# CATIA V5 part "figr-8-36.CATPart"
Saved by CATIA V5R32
Part number: Part1
Bounding box of the stored display mesh (mm): x -75 to 75, y -75 to 75, z 0 to 20
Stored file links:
  D:\PROJECTS\Project 2022\CATIA V5 6R 2022\Resources\Part Files\c08_catia_v5_6r2022_prt\figr-8-36.CATPart
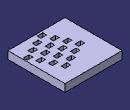
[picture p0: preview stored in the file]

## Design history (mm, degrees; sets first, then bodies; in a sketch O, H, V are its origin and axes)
Body1 (main body)
  Sketch1 on xy-plane, origin (0, 0, 0), H (1, 0, 0), V (0, 1, 0)
    line L1 (-75, 75) -> (75, 75)
    line L2 (75, 75) -> (75, -75)
    line L3 (75, -75) -> (-75, -75)
    line L4 (-75, -75) -> (-75, 75)
    axis line L5 (75, -75) -> (-75, 75)
    length L3 = 150
    length L2 = 150
    horizontal: L1 H, L3 H
    vertical: L2 V, L4 V
    midpoint: O L5
  Pad1: profile Sketch1, direction (0, 0, 1), length 20
  Sketch2 on face of Pad1, origin (0, 0, 20), H (1, 0, 0), V (0, 1, 0)
    line L1 (25, 40) -> (40, 40)
    line L2 (40, 40) -> (40, 30)
    line L3 (40, 30) -> (25, 30)
    line L4 (25, 30) -> (25, 40)
    reference projected line E1 (75, -75) -> (75, 75) from edge [face of Pad1 | face of Pad1]
    reference projected line E2 (75, 75) -> (-75, 75) from edge [face of Pad1 | face of Pad1]
    length L3 = 15
    length L4 = 10
    distance L2 E1 = 35
    distance L1 E2 = 35
    horizontal: L1 H, L3 H
    vertical: L2 V, L4 V
  Pocket1: profile Sketch2, direction (0, 0, -1), through (limit type 3)
  RectPattern1: of Pocket1, direction 1 instances 4, spacing 25, along edge [face of Pad1 | face of Pad1] reversed, direction 2 instances 4, spacing 25, along edge [face of Pad1 | face of Pad1], rotation -25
